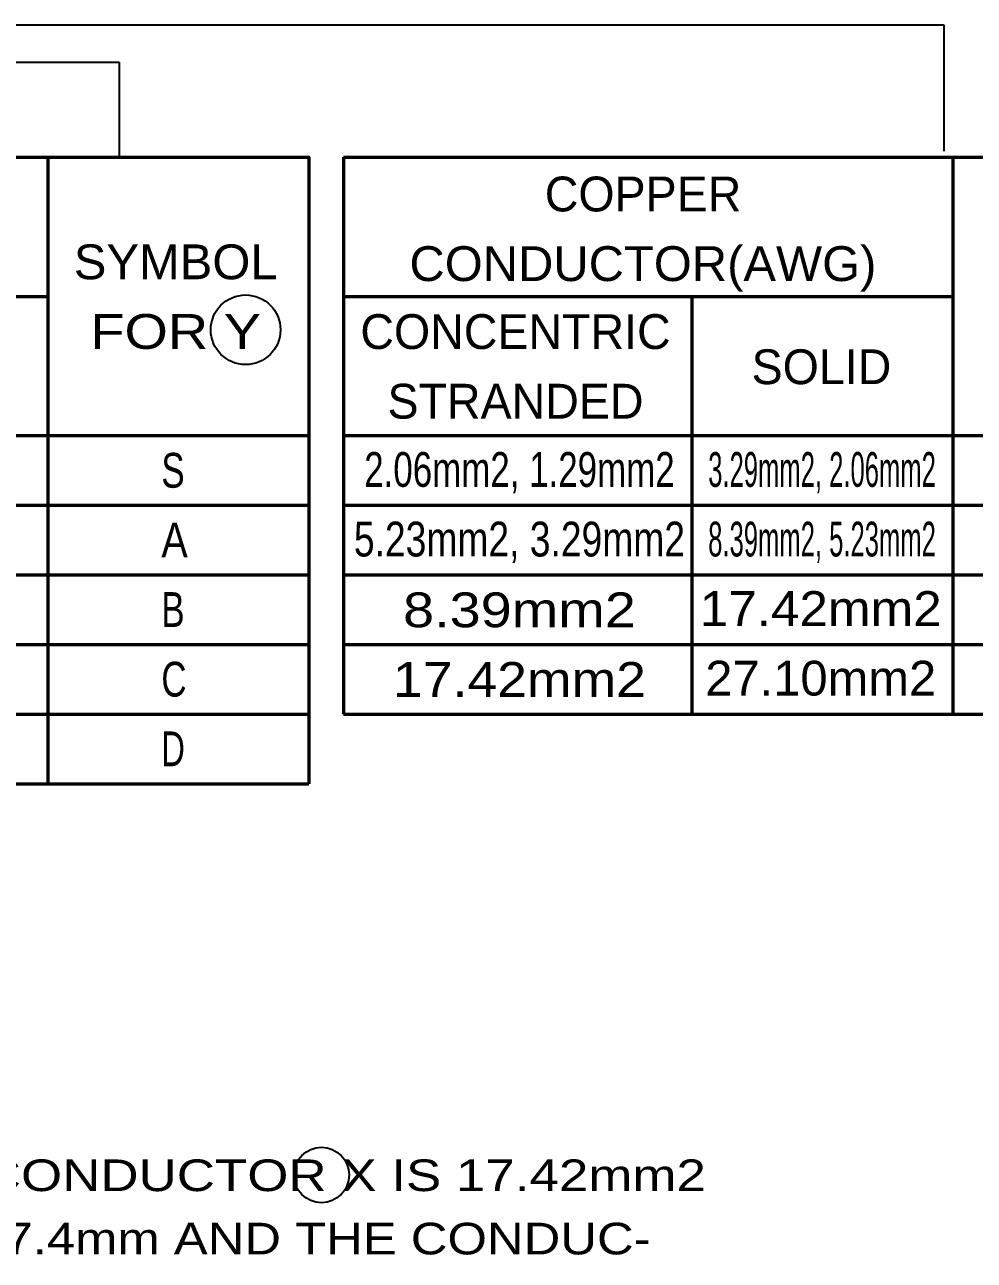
# Model space of a CAD drawing. Extents: x -32 to 824, y -6 to 538.
# Drawn here: x 441.4 to 513.4, y 268.1 to 361.8 of the extents above; entities that cross this region are included whole.
import ezdxf
from ezdxf.enums import TextEntityAlignment as Align

# ---------------------------------------------------------------- set-up
doc = ezdxf.new("R2010")
doc.units = 0
doc.header["$LTSCALE"] = 1.1
doc.layers.add('1', color=7, linetype='Continuous', lineweight=53)

msp = doc.modelspace()

# ---------------------------------------------------------------- linework, layer by layer
at = {"layer": '1', "lineweight": 35}
for p, q in [((404.885, 361.818), (511.085, 361.818)), ((511.085, 361.818), (511.085, 352.218)), ((396.989, 358.968), (448.542, 358.968)), ((448.542, 358.968), (448.542, 351.768))]:
    msp.add_line(p, q, dxfattribs=at)
at = {"layer": '1'}
for p, q in [((443.115, 351.778), (443.115, 304.258)), ((465.555, 351.778), (465.555, 309.538)), ((465.555, 351.778), (531.555, 351.778)), ((511.755, 351.778), (511.755, 309.538)), ((403.515, 341.218), (443.115, 341.218)), ((465.555, 341.218), (511.755, 341.218)), ((491.955, 341.218), (491.955, 309.538)), ((403.515, 330.658), (462.915, 330.658)), ((465.555, 330.658), (531.555, 330.658)), ((403.515, 325.378), (462.915, 325.378)), ((465.555, 325.378), (531.555, 325.378)), ((403.515, 320.098), (462.915, 320.098)), ((465.555, 320.098), (531.555, 320.098)), ((403.515, 314.818), (462.915, 314.818)), ((465.555, 314.818), (531.555, 314.818)), ((403.515, 309.538), (462.915, 309.538)), ((465.555, 309.538), (531.555, 309.538)), ((403.515, 304.258), (462.915, 304.258))]:
    msp.add_line(p, q, dxfattribs=at)
msp.add_lwpolyline([(403.515, 351.778), (462.915, 351.778), (462.915, 304.258)], dxfattribs=at)
at = {"layer": '1', "lineweight": 35}
for centre, radius in [((458.124, 338.682), 2.64), ((463.879, 274.586), 2.1)]:
    msp.add_circle(centre, radius, dxfattribs=at)

# ---------------------------------------------------------------- texts
at = {"layer": '1'}
for s, p in [('COPPER', (488.268, 347.659)), ('CONCENTRIC', (478.595, 337.225)), ('STRANDED', (478.595, 331.945))]:
    msp.add_text(s, height=2.64, dxfattribs=at).set_placement(p, align=Align.CENTER)
for s, width, p in [('SYMBOL', 1.05, (452.822, 342.516)), ('CONDUCTOR(AWG)', 1.05, (488.258, 342.379)), ('FOR Y', 1.2, (452.822, 337.236)), ('2.06mm2, 1.29mm2', 0.75, (478.893, 326.771)), ('3.29mm2, 2.06mm2', 0.55, (501.842, 326.771)), ('5.23mm2, 3.29mm2', 0.8, (478.893, 321.491)), ('8.39mm2, 5.23mm2', 0.55, (501.842, 321.491)), ('8.39mm2', 1.2, (478.893, 316.124)), ('17.42mm2', 1.1, (501.744, 316.221)), ('17.42mm2', 1.15, (478.893, 310.844)), ('27.10mm2', 1.05, (501.744, 310.942))]:
    msp.add_text(s, height=2.64, dxfattribs=dict(at, width=width)).set_placement(p, align=Align.CENTER)
msp.add_text('SOLID', height=2.64, dxfattribs=at).set_placement((496.5, 334.559))
for s, height, width, p in [('S', 2.64, 0.75, (451.735, 326.706)), ('A', 2.64, 0.85, (451.735, 321.426)), ('B', 2.64, 0.75, (451.735, 316.146)), ('C', 2.64, 0.75, (451.735, 310.866)), ('D', 2.64, 0.7, (451.735, 305.586)), ('IF THE LINE OUTSIDE DIAMETER W IS 10.7mm AND THE CONDUCTOR X IS 17.42mm2', 2.4, 1.25, (329.421, 273.363)), ('STRANDED, AND THE LOAD SIDE OUTSIDE DIAMETER Y IS 7.4mm AND THE CONDUC-', 2.4, 1.2, (329.421, 268.563))]:
    msp.add_text(s, height=height, dxfattribs=dict(at, width=width)).set_placement(p)

doc.saveas('drawing.dxf')
